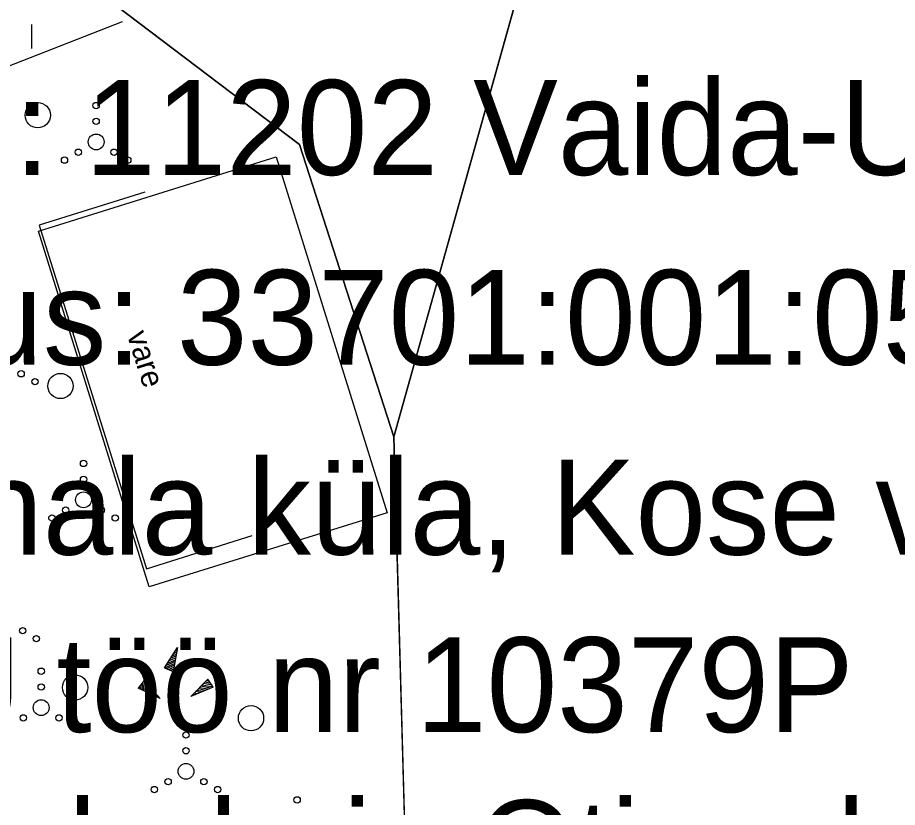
# Model space of a CAD drawing. Extents: x 554947 to 555436, y 6564938 to 6565792.
# Drawn here: x 555044.71 to 555072.52, y 6565611.19 to 6565636.15 of the extents above; entities that cross this region are included whole.
import ezdxf

# ---------------------------------------------------------------- set-up
doc = ezdxf.new("R2010")
doc.units = 0
for name, color, linetype in [('HALJASTUS', 7, 'Continuous'), ('HOONE', 7, 'Continuous'), ('Hoone Vare', 7, 'Continuous'), ('PIIR', 7, 'Continuous'), ('RELJEEF', 7, 'Continuous'), ('VORMISTUS_2', 7, 'Continuous')]:
    doc.layers.add(name, color=color, linetype=linetype)

msp = doc.modelspace()

# ---------------------------------------------------------------- linework, layer by layer
at = {"layer": 'HALJASTUS'}
msp.add_line((555045.155, 6565635.942), (555045.155, 6565635.181), dxfattribs=at)
msp.add_lwpolyline([(555057.023, 6565609.855), (555058.586, 6565605.616), (555058.613, 6565599.497), (555057.015, 6565597.532), (555043.839, 6565605.146), (555043.23, 6565610.761), (555037.198, 6565618.427), (555042.201, 6565623.493), (555040.415, 6565628.763), (555044.392, 6565634.613), (555048.032, 6565636.033)], dxfattribs=at)
for centre, radius in [((555045.349, 6565633.07), 0.4), ((555047.195, 6565633.376), 0.1), ((555047.195, 6565632.876), 0.1), ((555047.195, 6565632.226), 0.25), ((555046.63, 6565631.901), 0.1), ((555047.76, 6565631.901), 0.1), ((555046.195, 6565631.651), 0.1), ((555048.195, 6565631.651), 0.1), ((555044.825, 6565624.898), 0.1), ((555045.26, 6565624.648), 0.1), ((555046.066, 6565624.512), 0.4), ((555046.797, 6565622.064), 0.1), ((555046.797, 6565621.564), 0.1), ((555046.797, 6565620.914), 0.25), ((555046.232, 6565620.589), 0.1), ((555047.362, 6565620.589), 0.1), ((555045.797, 6565620.339), 0.1), ((555047.797, 6565620.339), 0.1), ((555044.872, 6565616.779), 0.1), ((555045.307, 6565616.529), 0.1), ((555045.458, 6565615.498), 0.1), ((555046.529, 6565614.984), 0.4), ((555045.458, 6565614.998), 0.1), ((555045.458, 6565614.348), 0.25), ((555052.091, 6565614.014), 0.4), ((555044.893, 6565614.023), 0.1), ((555046.023, 6565614.023), 0.1), ((555046.458, 6565613.773), 0.1), ((555050.035, 6565613.484), 0.1), ((555050.035, 6565612.984), 0.1), ((555050.035, 6565612.334), 0.25), ((555049.47, 6565612.009), 0.1), ((555050.6, 6565612.009), 0.1), ((555049.035, 6565611.759), 0.1), ((555051.035, 6565611.759), 0.1), ((555053.549, 6565611.433), 0.1)]:
    msp.add_circle(centre, radius, dxfattribs=at)
at = {"layer": 'HOONE'}
msp.add_lwpolyline([(555048.732, 6565630.638), (555045.392, 6565629.592), (555048.79, 6565618.739), (555052.13, 6565619.785)], dxfattribs=at)
at = {"layer": 'Hoone Vare'}
msp.add_lwpolyline([(555056.391, 6565620.508), (555048.876, 6565618.166), (555045.371, 6565629.41), (555052.886, 6565631.752)], close=True, dxfattribs=at)
at = {"layer": 'PIIR'}
for points in [[(555016.055, 6565654.913), (555030.24, 6565648.23), (555043.11, 6565640.11), (555053.62, 6565632.14), (555056.61, 6565622.91), (555057.22, 6565600.73), (555060.42, 6565583.26), (555065.78, 6565566.7), (555076.76, 6565542.38), (555113.82, 6565475.68), (554946.63, 6565420.78), (554981.01, 6565316.76), (555160.07, 6565375.54), (555166.64, 6565360.5), (555167.67, 6565357.913)], [(555045.31, 6565654.913), (555047.17, 6565654.02), (555063.43, 6565647.29), (555056.61, 6565622.91), (555053.62, 6565632.14), (555043.11, 6565640.11), (555030.24, 6565648.23), (555016.055, 6565654.913)], [(555144.16, 6565410.6), (555124.27, 6565454.45), (555113.82, 6565475.68), (555076.76, 6565542.38), (555065.78, 6565566.7), (555060.42, 6565583.26), (555057.22, 6565600.73), (555056.61, 6565622.91), (555063.43, 6565647.29), (555114.24, 6565634), (555129.77, 6565611.2), (555130.73, 6565621.32), (555138.66, 6565615.26), (555160.12, 6565598.86), (555193.24, 6565604.68), (555193.7, 6565602.7), (555225.47, 6565605.89), (555234.35, 6565605.6), (555251.24, 6565598.48), (555330.71, 6565538.85), (555343.81, 6565536.56), (555350.68, 6565540.44), (555361.56, 6565549.57), (555393.069, 6565582.099)]]:
    msp.add_lwpolyline(points, dxfattribs=at)
at = {"layer": 'RELJEEF'}
for p, q in [((555049.351, 6565615.607), (555049.771, 6565616.247)), ((555049.601, 6565615.982), (555049.731, 6565616.042)), ((555049.771, 6565616.247), (555049.631, 6565615.492)), ((555049.646, 6565616.057), (555049.746, 6565616.097)), ((555049.696, 6565616.132), (555049.756, 6565616.157)), ((555049.746, 6565616.207), (555049.766, 6565616.217)), ((555049.401, 6565615.682), (555049.686, 6565615.802)), ((555049.451, 6565615.757), (555049.701, 6565615.862)), ((555049.501, 6565615.832), (555049.626, 6565615.887)), ((555049.551, 6565615.907), (555049.721, 6565615.982)), ((555049.626, 6565615.887), (555049.711, 6565615.922)), ((555049.351, 6565615.607), (555049.676, 6565615.747)), ((555049.351, 6565615.607), (555049.631, 6565615.492)), ((555049.351, 6565615.607), (555049.351, 6565615.607)), ((555049.416, 6565615.582), (555049.666, 6565615.687)), ((555049.481, 6565615.552), (555049.656, 6565615.627)), ((555049.551, 6565615.527), (555049.646, 6565615.567)), ((555049.616, 6565615.502), (555049.631, 6565615.507)), ((555048.709, 6565615.207), (555048.524, 6565614.967)), ((555048.709, 6565615.207), (555049.214, 6565614.637)), ((555048.709, 6565615.207), (555048.754, 6565614.857)), ((555048.709, 6565615.207), (555048.709, 6565615.207)), ((555050.189, 6565614.702), (555050.729, 6565615.247)), ((555050.739, 6565615.232), (555050.719, 6565615.232)), ((555050.899, 6565614.997), (555050.729, 6565615.247)), ((555049.214, 6565614.637), (555048.524, 6565614.967)), ((555048.534, 6565614.982), (555048.539, 6565614.962)), ((555048.579, 6565615.037), (555048.594, 6565614.937)), ((555048.624, 6565615.097), (555048.649, 6565614.912)), ((555048.664, 6565615.152), (555048.699, 6565614.882)), ((555048.769, 6565615.142), (555048.809, 6565614.832)), ((555048.829, 6565615.072), (555048.864, 6565614.807)), ((555048.889, 6565615.007), (555048.904, 6565614.867)), ((555048.944, 6565614.937), (555048.974, 6565614.752)), ((555050.899, 6565614.997), (555050.189, 6565614.702)), ((555050.514, 6565614.917), (555050.424, 6565614.937)), ((555050.729, 6565614.927), (555050.464, 6565614.977)), ((555050.814, 6565614.962), (555050.509, 6565615.022)), ((555050.899, 6565614.997), (555050.549, 6565615.062)), ((555050.859, 6565615.052), (555050.594, 6565615.107)), ((555050.819, 6565615.112), (555050.634, 6565615.147)), ((555050.779, 6565615.172), (555050.679, 6565615.192)), ((555050.899, 6565614.997), (555050.899, 6565614.997)), ((555048.904, 6565614.867), (555048.919, 6565614.777)), ((555049.004, 6565614.872), (555049.024, 6565614.727)), ((555049.064, 6565614.802), (555049.079, 6565614.702)), ((555049.124, 6565614.737), (555049.134, 6565614.672)), ((555049.184, 6565614.667), (555049.189, 6565614.647)), ((555050.229, 6565614.717), (555050.214, 6565614.722)), ((555050.314, 6565614.752), (555050.254, 6565614.767)), ((555050.399, 6565614.787), (555050.294, 6565614.807)), ((555050.479, 6565614.822), (555050.339, 6565614.852)), ((555050.564, 6565614.857), (555050.379, 6565614.892)), ((555050.649, 6565614.892), (555050.514, 6565614.917))]:
    msp.add_line(p, q, dxfattribs=at)

# ---------------------------------------------------------------- texts
at = {"layer": 'HOONE'}
msp.add_text('vare', height=0.7, rotation=287.3428, dxfattribs=at).set_placement((555048.163, 6565626.139))
at = {"layer": 'VORMISTUS_2'}
for s, p in [('Kinnistu nimi: 11202 Vaida-Urge tee', (555021.874, 6565631.182)), ('Katastritunnus: 33701:001:0541', (555021.874, 6565625.182)), ('Asukoht: Tuhala küla, Kose vald, Harju maakond', (555021.874, 6565619.182))]:
    msp.add_text(s, height=3, dxfattribs=at).set_placement(p)
for s, p in [('Kirjanurk OÜ töö nr 10379P', (555021.859, 6565613.572)), ('Kose vald, Tuhala ja Otiveski elurajooni sideühendus', (555021.782, 6565608.425))]:
    msp.add_text(s, height=3, rotation=360, dxfattribs=at).set_placement(p)

doc.saveas('drawing.dxf')
